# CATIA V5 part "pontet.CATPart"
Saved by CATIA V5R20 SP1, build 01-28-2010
Part number: pontet
Bounding box of the stored display mesh (mm): x 0 to 7.5, y -10 to -5, z 10 to 22.5
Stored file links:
  F:\Pro\Emplois\1_Chercheur\ThinkMOTION\MMS\MMS_GR1\abruchon\Catia\pontet.CATPart
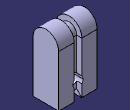
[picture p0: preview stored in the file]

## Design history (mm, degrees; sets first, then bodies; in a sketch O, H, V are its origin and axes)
Body1 (main body)
  Sketch1 on yz-plane, origin (0, 0, 0), H (0, 1, 0), V (0, 0, 1)
    line L1 (-5, 20) -> (-5, 10)
    line L2 (-5, 10) -> (-10, 10)
    line L3 (-10, 10) -> (-10, 20)
    arc A1 centre (-7.5, 20) radius 2.5 from (-5, 20) to (-10, 20) ccw
    length L1 = 10
    length L2 = 5
    radius A1 = 2.5
    horizontal: L2 H
    vertical: L1 V, L3 V
  Pad1: profile Sketch1, direction (1, 0, 0), length 7.5
  Sketch2 on face of Pad1 from Sketch1.L2, origin (0, 0, 10), H (1, 0, 0), V (0, -1, 0)
    line L1 (3, 6) -> (4.5, 6)
    line L2 (4.5, 6) -> (4.5, 5)
    line L3 (4.5, 5) -> (3, 5)
    line L4 (3, 5) -> (3, 6)
    reference projected line E1 (0, 10) -> (0, 5) from edge [start face of Pad1 | face of Pad1 from Sketch1.L2]
    reference projected line E2 (7.5, 10) -> (7.5, 5) from edge [face of Pad1 from Sketch1.L2 | end face of Pad1]
    reference projected line E3 (0, 5) -> (7.5, 5) from edge [face of Pad1 from Sketch1.L1 | face of Pad1 from Sketch1.L2]
    distance L4 E1 = 3
    distance E2 L2 = 3
    distance L3 E3 = 0
    length L2 = 1
    horizontal: L1 H, L3 H
    vertical: L2 V, L4 V
  Sketch3 on end face of Pad1, origin (7.5, 0, 0), H (0, 1, 0), V (0, 0, 1)
  Slot1: profile Sketch2, centre curve Sketch3
  Sketch4 on face of Pad1 from Sketch1.L1, origin (0, -5, 0), H (-1, 0, 0), V (0, 0, 1)
    circle A1 centre (-3.75, 13) radius 1
    point P1 (-3.75, 13)
    reference projected line E1 (0, 20) -> (-7.5, 20) from edge [face of Pad1 from Sketch1.A1 | face of Pad1 from Sketch1.L1]
    reference projected line E2 (-7.5, 10) -> (-7.5, 20) from edge [face of Pad1 from Sketch1.L1 | end face of Pad1]
    radius A1 = 1
    distance A1 E1 = 6
    distance P1 E2 = 3.75
  Pocket1: profile Sketch4, direction (0, -1, 0), up to face of Pad1 from Sketch1.L3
